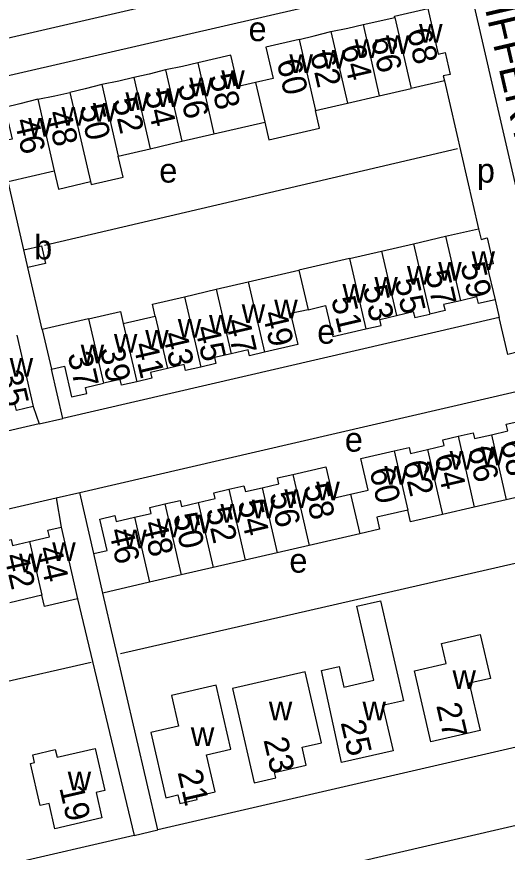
# Model space of a CAD drawing. Extents: x 155696 to 157795, y 382328 to 384028.
# Drawn here: x 157204.2 to 157284.9, y 383313 to 383450.5 of the extents above; entities that cross this region are included whole.
import ezdxf

# ---------------------------------------------------------------- set-up
doc = ezdxf.new("R2010")
doc.units = 0
for name, color, linetype in [('BLT_Basislijn', 7, 'Continuous'), ('BLT_Bebouwing', 7, 'Continuous'), ('BLT_Centroide', 7, 'Continuous'), ('BLT_Huisnummer', 7, 'Continuous'), ('BLT_Huisnummer_ tussenligend', 7, 'Continuous'), ('BLT_Onderverdeling_panden', 7, 'Continuous'), ('BLT_Straatnaam', 7, 'Continuous')]:
    doc.layers.add(name, color=color, linetype=linetype)

msp = doc.modelspace()

# ---------------------------------------------------------------- linework, layer by layer
at = {"layer": 'BLT_Basislijn'}
for p, q in [((157208.72, 383412.84), (157276.75, 383428.75)), ((157207.83, 383383.45), (157211.73, 383384.35)), ((157210.64, 383371.27), (157214.54, 383372.17)), ((157292.46, 383361.94), (157221.24, 383345.63)), ((157216.43, 383344.18), (157153.46, 383329.87)), ((157223.47, 383315.74), (157227.37, 383316.64))]:
    msp.add_line(p, q, dxfattribs=at)
for points in [[(157269.42, 383462.34), (157197.55, 383445.74)], [(157198.9, 383439.89), (157270.77, 383456.49)], [(157270.77, 383456.49), (157278.8, 383455.05), (157290.9, 383402.64), (157291.12, 383401.66), (157291.11, 383400.64), (157290.68, 383398.63), (157289.76, 383397.14), (157288.54, 383396.04), (157286.94, 383395.36), (157285, 383394.89), (157283.59, 383400.95)], [(157274.59, 383439.93), (157280.21, 383415.57)], [(157205.33, 383412.09), (157202.73, 383423.33)], [(157208.34, 383398.98), (157206.01, 383409.19)], [(157282.92, 383403.88), (157283.59, 383400.95)], [(157283.59, 383400.95), (157211.73, 383384.35)], [(157211.73, 383384.35), (157209.86, 383392.48)], [(157214.54, 383372.17), (157286.41, 383388.77)], [(157206.87, 383386.31), (157207.83, 383383.45), (157143.75, 383368.65), (157143.36, 383371.64)], [(157216.87, 383362.13), (157214.54, 383372.17)], [(157146.56, 383356.47), (157210.64, 383371.27), (157211.45, 383366.46)], [(157227.37, 383316.64), (157218.35, 383355.62)], [(157214.18, 383354.66), (157223.47, 383315.74), (157159.39, 383300.93), (157151.43, 383336.7)], [(157299.24, 383333.24), (157227.37, 383316.64)], [(157230.18, 383304.46), (157302.05, 383321.06)]]:
    msp.add_lwpolyline(points, dxfattribs=at)
at = {"layer": 'BLT_Bebouwing'}
for p, q in [((157261.18, 383449.15), (157266.4, 383450.35)), ((157258.62, 383436.24), (157263.84, 383437.45)), ((157263.84, 383437.45), (157269.11, 383438.66)), ((157253.33, 383435.03), (157258.62, 383436.24)), ((157231.37, 383429.95), (157236.63, 383431.16)), ((157226.11, 383428.73), (157231.37, 383429.95)), ((157220.85, 383427.52), (157226.11, 383428.73)), ((157269.5, 383413.1), (157274.76, 383414.32)), ((157264.24, 383411.89), (157269.5, 383413.1)), ((157206.01, 383409.19), (157205.33, 383412.09)), ((157258.97, 383410.67), (157264.24, 383411.89)), ((157237.02, 383405.6), (157242.28, 383406.82)), ((157221.71, 383399.97), (157226.97, 383401.19)), ((157208.34, 383398.98), (157209.86, 383392.48)), ((157284.76, 383370.96), (157279.5, 383369.75)), ((157279.5, 383369.75), (157274.24, 383368.53)), ((157252.31, 383363.46), (157247.03, 383362.25)), ((157247.03, 383362.25), (157241.77, 383361.03)), ((157241.77, 383361.03), (157236.5, 383359.82)), ((157236.5, 383359.82), (157231.24, 383358.6)), ((157208.3, 383355.26), (157203.04, 383354.04)), ((157251.63, 383342.66), (157239.68, 383339.9)), ((157254.33, 383330.97), (157251.63, 383342.66)), ((157239.68, 383339.9), (157240.57, 383336.11)), ((157240.57, 383336.11), (157243.27, 383324.42)), ((157251.17, 383330.24), (157254.33, 383330.97)), ((157251.84, 383327.32), (157251.17, 383330.24)), ((157243.27, 383324.42), (157246.83, 383325.23))]:
    msp.add_line(p, q, dxfattribs=at)
for points in [[(157266.4, 383450.35), (157266.36, 383450.56), (157271.83, 383451.83)], [(157271.83, 383451.83), (157273.57, 383444.31), (157274.68, 383444.57), (157275.51, 383440.95), (157274.4, 383440.7), (157274.59, 383439.93)], [(157255.9, 383448), (157258.69, 383448.57), (157261.18, 383449.15)], [(157250.66, 383446.72), (157253.15, 383447.29), (157255.9, 383448)], [(157250.66, 383446.72), (157245.19, 383445.45), (157246.4, 383440.28), (157243.5, 383439.61)], [(157243.5, 383439.61), (157240.6, 383438.95), (157239.43, 383444.12), (157233.97, 383442.86)], [(157228.68, 383441.72), (157225.94, 383441.01), (157223.45, 383440.43)], [(157233.97, 383442.86), (157231.47, 383442.28), (157228.68, 383441.72)], [(157223.45, 383440.43), (157220.95, 383439.85), (157218.16, 383439.3)], [(157218.16, 383439.3), (157215.42, 383438.58), (157212.92, 383438)], [(157274.59, 383439.93), (157269.11, 383438.66)], [(157207.62, 383436.86), (157210.43, 383437.42), (157212.92, 383438)], [(157207.62, 383436.86), (157204.69, 383436.1), (157202.2, 383435.52), (157203.39, 383430.33), (157201.22, 383429.84)], [(157245.01, 383433.11), (157245.68, 383430.21), (157254, 383432.13), (157253.33, 383435.03)], [(157236.63, 383431.16), (157245.01, 383433.11)], [(157216.31, 383423.34), (157216.43, 383422.82), (157221.69, 383424.04), (157220.85, 383427.52)], [(157202.73, 383423.33), (157210.32, 383425.09)], [(157210.32, 383425.09), (157211.04, 383422.09), (157216.31, 383423.34)], [(157274.76, 383414.32), (157280.21, 383415.57)], [(157280.21, 383415.57), (157280.61, 383413.82), (157281.62, 383414.05), (157282.58, 383409.8), (157281.59, 383409.55), (157282.92, 383403.88)], [(157205.33, 383412.09), (157208.22, 383412.76), (157208.89, 383409.86), (157206.01, 383409.19)], [(157258.97, 383410.67), (157250.62, 383408.73)], [(157242.28, 383406.82), (157250.62, 383408.73)], [(157226.97, 383401.19), (157226.51, 383403.17), (157231.76, 383404.38)], [(157231.76, 383404.38), (157237.02, 383405.6)], [(157277.22, 383403.72), (157274.45, 383403.08), (157274.68, 383402.1), (157272.18, 383401.53)], [(157282.92, 383403.88), (157280.17, 383403.24), (157279.92, 383404.34), (157277.22, 383403.72)], [(157215.98, 383400.74), (157221.25, 383401.96), (157221.71, 383399.97)], [(157252.12, 383402.25), (157249.24, 383401.6), (157250.43, 383396.51), (157244.97, 383395.24)], [(157252.12, 383402.25), (157255, 383402.91), (157256.19, 383397.84), (157261.66, 383399.1)], [(157266.7, 383401.29), (157269.46, 383401.93), (157269.69, 383400.95), (157272.18, 383401.53)], [(157215.98, 383400.74), (157208.34, 383398.98)], [(157261.66, 383399.1), (157264.15, 383399.67), (157263.93, 383400.65), (157266.7, 383401.29)], [(157204.15, 383398.03), (157206.87, 383386.31)], [(157239.48, 383395), (157236.71, 383394.36), (157236.94, 383393.39), (157234.45, 383392.81)], [(157244.97, 383395.24), (157242.47, 383394.67), (157242.25, 383395.64), (157239.48, 383395)], [(157209.86, 383392.48), (157212.02, 383392.96), (157213.19, 383387.89), (157215.69, 383388.48), (157215.46, 383389.45), (157218.44, 383390.14)], [(157228.96, 383392.57), (157226.19, 383391.93), (157226.42, 383390.96), (157223.92, 383390.38)], [(157234.45, 383392.81), (157231.95, 383392.24), (157231.73, 383393.21), (157228.96, 383392.57)], [(157223.92, 383390.38), (157221.43, 383389.81), (157221.2, 383390.78), (157218.44, 383390.14)], [(157206.87, 383386.31), (157204.12, 383385.68), (157203.86, 383386.78), (157201.16, 383386.15)], [(157282.31, 383381.67), (157285.01, 383382.29), (157284.76, 383383.39), (157287.5, 383384.03)], [(157271.79, 383379.24), (157274.55, 383379.88), (157274.33, 383380.85), (157276.82, 383381.43)], [(157276.82, 383381.43), (157279.32, 383382.01), (157279.54, 383381.03), (157282.31, 383381.67)], [(157259.14, 383371.9), (157262.02, 383372.56), (157260.84, 383377.74), (157266.3, 383379)], [(157266.3, 383379), (157268.8, 383379.57), (157269.02, 383378.6), (157271.79, 383379.24)], [(157249.61, 383375.14), (157255.08, 383376.41), (157256.26, 383371.23), (157259.14, 383371.9)], [(157244.57, 383372.95), (157247.34, 383373.59), (157247.12, 383374.57), (157249.61, 383375.14)], [(157239.09, 383372.71), (157241.58, 383373.29), (157241.81, 383372.31), (157244.57, 383372.95)], [(157234.05, 383370.52), (157236.82, 383371.16), (157236.59, 383372.14), (157239.09, 383372.71)], [(157290.23, 383372.22), (157284.76, 383370.96)], [(157223.53, 383368.09), (157226.3, 383368.73), (157226.07, 383369.71), (157228.56, 383370.28)], [(157228.56, 383370.28), (157231.06, 383370.86), (157231.28, 383369.88), (157234.05, 383370.52)], [(157268.55, 383369.27), (157263.46, 383368.09), (157263.91, 383366.15), (157260.64, 383365.39)], [(157274.24, 383368.53), (157269, 383367.32), (157268.55, 383369.27)], [(157216.87, 383362.13), (157219.03, 383362.63), (157217.84, 383367.8), (157220.33, 383368.38), (157220.56, 383367.41), (157223.53, 383368.09)], [(157206.26, 383364.1), (157209.53, 383364.86), (157209.28, 383365.96), (157211.45, 383366.46)], [(157211.45, 383366.46), (157214.18, 383354.66)], [(157260.64, 383365.39), (157252.31, 383363.46)], [(157200.77, 383363.86), (157203.27, 383364.44), (157203.49, 383363.46), (157206.26, 383364.1)], [(157218.35, 383355.62), (157216.87, 383362.13)], [(157231.24, 383358.6), (157226, 383357.39)], [(157226, 383357.39), (157218.35, 383355.62)], [(157214.18, 383354.66), (157208.73, 383353.4), (157208.3, 383355.26)], [(157206.8, 383329.03), (157210.5, 383329.88), (157210.8, 383328.61), (157217.08, 383330.07), (157218.68, 383323.13), (157217.22, 383322.79), (157218.19, 383318.62), (157210.44, 383316.83), (157209.48, 383321), (157208.01, 383320.66), (157206.41, 383327.6), (157207.09, 383327.76), (157206.8, 383329.03)], [(157246.83, 383325.23), (157246.62, 383326.11), (157251.84, 383327.32)]]:
    msp.add_lwpolyline(points, dxfattribs=at)
for points in [[(157257.65, 383327.74), (157254.33, 383342.88), (157257.23, 383343.55), (157258.02, 383340.14), (157262.98, 383341.28), (157260.17, 383353.46), (157264.07, 383354.36), (157267.87, 383337.9), (157264.41, 383337.1), (157266.12, 383329.69)], [(157269.66, 383342.82), (157274.86, 383344.03), (157274.09, 383347.35), (157280.49, 383348.83), (157282.16, 383341.59), (157278.65, 383340.78), (157280.45, 383333), (157272.36, 383331.13)], [(157237, 383340.47), (157229.64, 383338.78), (157230.81, 383333.73), (157226.23, 383332.67), (157228.7, 383321.95), (157230.68, 383322.41), (157231.02, 383320.97), (157233.89, 383321.63), (157233.76, 383322.22), (157236.82, 383322.93), (157235.42, 383329.03), (157239.43, 383329.95)]]:
    msp.add_lwpolyline(points, close=True, dxfattribs=at)
at = {"layer": 'BLT_Onderverdeling_panden'}
for p, q in [((157266.4, 383450.35), (157269.11, 383438.66)), ((157261.18, 383449.15), (157263.84, 383437.45)), ((157255.9, 383448), (157258.62, 383436.24)), ((157250.66, 383446.72), (157253.33, 383435.03)), ((157228.68, 383441.72), (157231.37, 383429.95)), ((157233.97, 383442.86), (157236.63, 383431.16)), ((157223.45, 383440.43), (157226.11, 383428.73)), ((157218.16, 383439.3), (157220.85, 383427.52)), ((157243.5, 383439.61), (157245.01, 383433.11)), ((157212.92, 383438), (157216.31, 383423.34)), ((157207.62, 383436.86), (157210.32, 383425.09)), ((157274.76, 383414.32), (157277.22, 383403.72)), ((157269.5, 383413.1), (157272.18, 383401.53)), ((157264.24, 383411.89), (157266.7, 383401.29)), ((157258.97, 383410.67), (157261.66, 383399.1)), ((157250.62, 383408.73), (157252.12, 383402.25)), ((157242.28, 383406.82), (157244.97, 383395.24)), ((157231.76, 383404.38), (157234.45, 383392.81)), ((157237.02, 383405.6), (157239.48, 383395)), ((157215.98, 383400.74), (157218.44, 383390.14)), ((157226.97, 383401.19), (157228.96, 383392.57)), ((157221.71, 383399.97), (157223.92, 383390.38)), ((157276.82, 383381.43), (157279.5, 383369.75)), ((157282.31, 383381.67), (157284.76, 383370.96)), ((157266.3, 383379), (157268.55, 383369.27)), ((157271.79, 383379.24), (157274.24, 383368.53)), ((157244.57, 383372.95), (157247.03, 383362.25)), ((157239.09, 383372.71), (157241.77, 383361.03)), ((157259.14, 383371.9), (157260.64, 383365.39)), ((157228.56, 383370.28), (157231.24, 383358.6)), ((157234.05, 383370.52), (157236.5, 383359.82)), ((157223.53, 383368.09), (157226, 383357.39)), ((157206.26, 383364.1), (157208.3, 383355.26))]:
    msp.add_line(p, q, dxfattribs=at)
msp.add_lwpolyline([(157249.61, 383375.14), (157252.31, 383363.46)], dxfattribs=at)

# ---------------------------------------------------------------- texts
at = {"layer": 'BLT_Centroide'}
for s, p in [('e', (157242.33, 383446.44)), ('w', (157270.41, 383446.17)), ('w', (157264.95, 383444.33)), ('w', (157259.8, 383443.64)), ('w', (157254.42, 383441.91)), ('w', (157249.06, 383441.17)), ('w', (157237.84, 383438.58)), ('w', (157232.58, 383437.36)), ('w', (157222.06, 383434.94)), ('w', (157227.2, 383435.62)), ('w', (157216.69, 383433.19)), ('w', (157211.53, 383432.52)), ('w', (157206.06, 383430.72)), ('e', (157227.63, 383423.16)), ('p', (157279.92, 383423.16)), ('b', (157207.03, 383410.53)), ('w', (157279.05, 383408.8)), ('w', (157273.56, 383407.02)), ('w', (157268.42, 383406.34)), ('w', (157263.05, 383404.58)), ('w', (157257.8, 383403.39)), ('w', (157241.2, 383400.06)), ('w', (157246.56, 383400.8)), ('w', (157230.69, 383397.62)), ('w', (157235.83, 383398.3)), ('w', (157225.31, 383395.86)), ('e', (157253.64, 383396.65)), ('w', (157220.16, 383395.19)), ('w', (157214.69, 383393.42)), ('w', (157203, 383391.23)), ('e', (157258.18, 383378.89)), ('w', (157280.59, 383376.62)), ('w', (157275.44, 383375.92)), ('w', (157270.06, 383374.19)), ('w', (157264.7, 383373.45)), ('w', (157253.48, 383370.86)), ('w', (157248.23, 383369.64)), ('w', (157237.7, 383367.23)), ('w', (157242.86, 383367.91)), ('w', (157227.19, 383364.8)), ('w', (157232.33, 383365.47)), ('w', (157221.7, 383363)), ('w', (157210, 383360.89)), ('w', (157204.53, 383359.05)), ('e', (157249.05, 383358.98)), ('w', (157275.91, 383339.86)), ('w', (157245.67, 383334.69)), ('w', (157261.09, 383334.69)), ('w', (157232.83, 383330.44)), ('w', (157212.55, 383323.17))]:
    msp.add_text(s, height=4, dxfattribs=at).set_placement(p)
at = {"layer": 'BLT_Huisnummer'}
for s, rotation, p in [('68', 283.0062, (157268.37, 383448.15)), ('64', 283.0062, (157257.51, 383445.48)), ('60', 283.0062, (157246.94, 383443.08)), ('58', 283.0062, (157235.81, 383440.67)), ('54', 283.0062, (157225.17, 383437.89)), ('50', 283.0062, (157214.45, 383435.63)), ('46', 283.0062, (157203.74, 383433.37)), ('59', 283.0064, (157277.21, 383409.62)), ('55', 283.0064, (157266.34, 383407.05)), ('51', 283.0064, (157255.91, 383404.04)), ('49', 283.0064, (157244.6, 383401.66)), ('45', 283.0064, (157233.48, 383399.25)), ('41', 283.0064, (157223.31, 383396.5)), ('37', 283.0064, (157212.5, 383394.9)), ('35', 283.0064, (157201.03, 383391.82)), ('68', 283.0062, (157283.78, 383380.39)), ('64', 283.0062, (157272.91, 383378.18)), ('60', 283.0062, (157262.21, 383375.86)), ('58', 283.0062, (157251.38, 383373.2)), ('54', 283.0062, (157240.51, 383370.56)), ('50', 283.0062, (157229.89, 383368.42)), ('46', 283.0062, (157219.28, 383365.93)), ('44', 283.0062, (157207.52, 383362.95)), ('27', 283.0059, (157273.21, 383337.14)), ('25', 283.0085, (157257.47, 383334.33)), ('23', 283.0057, (157244.77, 383331.47)), ('21', 283.006, (157230.62, 383326.15)), ('19', 283.0062, (157211.15, 383323.59))]:
    msp.add_text(s, height=4, rotation=rotation, dxfattribs=at).set_placement(p)
at = {"layer": 'BLT_Huisnummer_ tussenligend'}
for s, rotation, p in [('66', 283.0062, (157262.45, 383446.75)), ('62', 283.0062, (157252.44, 383444.33)), ('56', 283.0062, (157230.66, 383439.16)), ('52', 283.0062, (157219.95, 383436.74)), ('48', 283.0062, (157209.1, 383434.63)), ('57', 283.0064, (157271.39, 383408.35)), ('53', 283.0064, (157261.12, 383405.85)), ('47', 283.0064, (157238.52, 383400.38)), ('43', 283.0064, (157228.17, 383398.23)), ('39', 283.0064, (157217.81, 383395.75)), ('66', 283.0062, (157278.38, 383379.37)), ('62', 283.0062, (157267.69, 383377.05)), ('56', 283.0062, (157245.73, 383371.93)), ('52', 283.0062, (157235.29, 383369.34)), ('48', 283.0062, (157224.85, 383367.12)), ('42', 283.0062, (157202.05, 383361.74))]:
    msp.add_text(s, height=4, rotation=rotation, dxfattribs=at).set_placement(p)
at = {"layer": 'BLT_Straatnaam'}
msp.add_text('NIEUWE SLIFFERTSESTRAAT', height=5, rotation=283.0066, dxfattribs=at).set_placement((157272.96, 383487.62))

doc.saveas('drawing.dxf')
